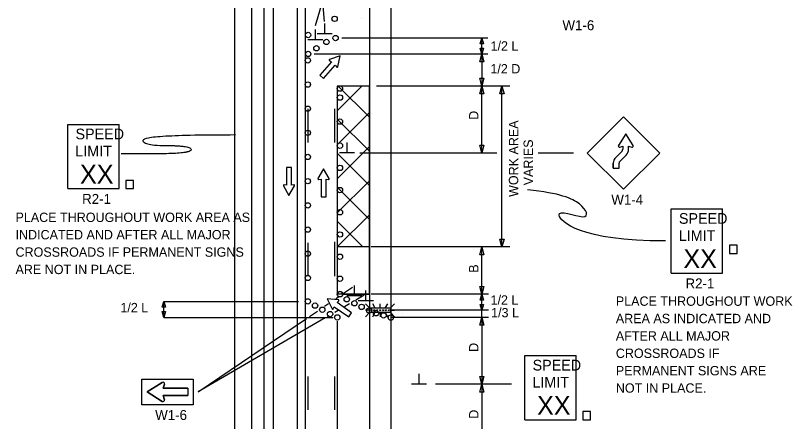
# Model space of a CAD drawing. Extents: x 16748 to 18296, y 7218 to 8262.
# Drawn here: x 16825 to 17405, y 7635 to 7938 of the extents above; entities that cross this region are included whole.
import ezdxf

# ---------------------------------------------------------------- set-up
doc = ezdxf.new("R2010")
doc.units = 0
for name, color, linetype in [('ALI_LEGAL_EX', 7, 'Continuous'), ('BORDER', 7, 'Continuous'), ('Level 42', 7, 'Continuous'), ('MT_SCRATCH_LEVEL_A', 7, 'Continuous'), ('MT_SCRATCH_LEVEL_E', 7, 'Continuous'), ('MT_STAGE_1A_NOTES', 7, 'Continuous'), ('PAVT_EDGE_EX', 7, 'Continuous'), ('TRAFFIC_SIGNS_PR', 7, 'Continuous'), ('TYPICAL_EX', 7, 'Continuous'), ('TYPICAL_TEXT_DIMEN_PR', 7, 'Continuous')]:
    doc.layers.add(name, color=color, linetype=linetype)

msp = doc.modelspace()

# ---------------------------------------------------------------- linework, layer by layer
at = {"layer": 'ALI_LEGAL_EX'}
msp.add_lwpolyline([(17089.08, 7668.47), (17089.08, 7653.92)], dxfattribs=at)
at = {"layer": 'BORDER'}
for p, q in [((17017.08, 8216.25), (17017.08, 7341.25)), ((17089.08, 8216.25), (17089.08, 7765.38)), ((17089.08, 7765.38), (17089.08, 7341.25))]:
    msp.add_line(p, q, dxfattribs=at)
at = {"layer": 'Level 42'}
for p, q in [((17083.1, 7935.93), (17083.1, 7935.93)), ((17063.22, 7923.81), (17063.22, 7923.81)), ((17087.08, 7729.95), (17087.08, 7729.95)), ((17073.87, 7718.33), (17073.87, 7718.33)), ((17079.7, 7715.13), (17079.7, 7715.13)), ((17108.91, 7717.79), (17108.91, 7717.79)), ((17114.05, 7715.71), (17114.05, 7715.71))]:
    msp.add_line(p, q, dxfattribs=at)
at = {"layer": 'MT_SCRATCH_LEVEL_A'}
for p, q in [((17041.08, 8216.25), (17041.08, 7341.25)), ((17089.09, 7885.6), (17065.08, 7885.6)), ((17066.01, 7773.88), (17066.06, 7774)), ((17065.08, 7709.73), (17065.08, 7341.25))]:
    msp.add_line(p, q, dxfattribs=at)
for points in [[(17065.08, 7885.6), (17065.08, 7765.51), (17065.08, 7729.95)], [(17043.08, 7868.47), (17043.08, 7843.47)], [(17063.08, 7868.47), (17063.08, 7843.47)], [(17043.08, 7768.47), (17043.08, 7743.47)], [(17063.08, 7769.08), (17063.08, 7743.47)], [(17043.08, 7668.47), (17043.08, 7643.47)], [(17063.08, 7668.47), (17063.08, 7643.47)]]:
    msp.add_lwpolyline(points, dxfattribs=at)
at = {"layer": 'MT_SCRATCH_LEVEL_E'}
for p, q in [((17067.13, 7908.18), (17059.25, 7905.49)), ((17067.13, 7908.18), (17059.25, 7905.49)), ((17065.43, 7900.01), (17067.13, 7908.18)), ((17065.43, 7900.01), (17067.13, 7908.18)), ((17060.69, 7903.71), (17051.91, 7893.78)), ((17060.69, 7903.71), (17051.91, 7893.78)), ((17054.71, 7891.31), (17063.5, 7901.23)), ((17054.71, 7891.31), (17063.5, 7901.23)), ((17059.15, 7904.65), (17060.69, 7903.71)), ((17059.15, 7904.65), (17060.69, 7903.71)), ((17063.5, 7901.23), (17064.62, 7899.82)), ((17063.5, 7901.23), (17064.62, 7899.82)), ((17051.91, 7893.78), (17054.71, 7891.31)), ((17051.91, 7893.78), (17054.71, 7891.31)), ((17030.82, 7824.7), (17027.08, 7824.7)), ((17027.08, 7824.7), (17027.08, 7811.45)), ((17030.82, 7824.7), (17027.08, 7824.7)), ((17027.08, 7824.7), (17027.08, 7811.45)), ((17030.82, 7811.45), (17030.82, 7824.7)), ((17030.82, 7811.45), (17030.82, 7824.7)), ((17054.76, 7823.64), (17050.65, 7816.4)), ((17054.76, 7823.64), (17050.65, 7816.4)), ((17058.91, 7816.4), (17054.76, 7823.64)), ((17058.91, 7816.4), (17054.76, 7823.64)), ((17051.14, 7815.72), (17052.91, 7816.03)), ((17051.14, 7815.72), (17052.91, 7816.03)), ((17052.91, 7816.03), (17052.91, 7802.78)), ((17052.91, 7816.03), (17052.91, 7802.78)), ((17056.65, 7802.78), (17056.65, 7816.03)), ((17056.65, 7816.03), (17058.43, 7815.72)), ((17056.65, 7802.78), (17056.65, 7816.03)), ((17056.65, 7816.03), (17058.43, 7815.72)), ((17024.82, 7811.08), (17028.97, 7803.84)), ((17024.82, 7811.08), (17028.97, 7803.84)), ((17027.08, 7811.45), (17025.3, 7811.76)), ((17027.08, 7811.45), (17025.3, 7811.76)), ((17028.97, 7803.84), (17033.08, 7811.08)), ((17028.97, 7803.84), (17033.08, 7811.08)), ((17032.6, 7811.76), (17030.82, 7811.45)), ((17032.6, 7811.76), (17030.82, 7811.45)), ((17052.91, 7802.78), (17056.65, 7802.78)), ((17052.91, 7802.78), (17056.65, 7802.78)), ((17057.62, 7726.47), (17061.2, 7718.96)), ((17065.93, 7725.73), (17057.62, 7726.47)), ((17057.62, 7726.47), (17061.2, 7718.96)), ((17065.93, 7725.73), (17057.62, 7726.47)), ((17064.94, 7723.67), (17066.21, 7724.94)), ((17064.94, 7723.67), (17066.21, 7724.94)), ((17075.81, 7716.08), (17064.94, 7723.67)), ((17075.81, 7716.08), (17064.94, 7723.67)), ((17062.03, 7718.96), (17062.79, 7720.6)), ((17062.03, 7718.96), (17062.79, 7720.6)), ((17062.79, 7720.6), (17073.66, 7713.01)), ((17062.79, 7720.6), (17073.66, 7713.01)), ((17073.66, 7713.01), (17075.81, 7716.08)), ((17073.66, 7713.01), (17075.81, 7716.08))]:
    msp.add_line(p, q, dxfattribs=at)
for centre, start, end in [((17059.4, 7905.05), 108.90425, 238.44322), ((17059.4, 7905.05), 108.90425, 238.44322), ((17064.97, 7900.11), 218.5156, 348.25253), ((17064.97, 7900.11), 218.5156, 348.25253), ((17051.06, 7816.18), 150.42484, 279.96381), ((17051.06, 7816.18), 150.42484, 279.96381), ((17058.5, 7816.18), 260.03619, 29.77312), ((17058.5, 7816.18), 260.03619, 29.77312), ((17025.23, 7811.3), 80.03619, 209.77312), ((17025.23, 7811.3), 80.03619, 209.77312), ((17032.67, 7811.3), 330.42484, 99.96381), ((17032.67, 7811.3), 330.42484, 99.96381), ((17065.88, 7725.26), 315.10498, 84.84191), ((17065.88, 7725.26), 315.10498, 84.84191), ((17061.62, 7719.16), 205.49363, 335.0326), ((17061.62, 7719.16), 205.49363, 335.0326)]:
    msp.add_arc(centre, 0.463, start, end, dxfattribs=at)
at = {"layer": 'MT_STAGE_1A_NOTES'}
msp.add_lwpolyline([(17069.08, 7729.95), (17069.42, 7729.95), (17076.66, 7729.95), (17077.86, 7729.95), (17086.42, 7729.95), (17089.08, 7729.95), (17089.08, 7765.38), (17065.08, 7765.38), (17065.08, 7729.95)], dxfattribs=at)
msp.add_arc((17067.08, 7729.95), 2, 0, 180, dxfattribs=at)
at = {"layer": 'PAVT_EDGE_EX'}
for p, q in [((16988.15, 8262.34), (16988.15, 7433.15)), ((17010.15, 8262.34), (17010.15, 7433.15)), ((17035.15, 8262.34), (17035.15, 7433.15)), ((17001.08, 8216.25), (17001.08, 7341.25)), ((17105.08, 8216.25), (17105.08, 7341.25)), ((17065.08, 7867.2), (17083.48, 7885.6)), ((17089.09, 7862.29), (17065.78, 7885.6)), ((17089.09, 7765.38), (17089.09, 7885.6)), ((17065.08, 7841.75), (17089.09, 7865.76)), ((17089.09, 7836.83), (17065.08, 7860.84)), ((17065.08, 7816.29), (17089.09, 7840.3)), ((17089.09, 7811.37), (17065.08, 7835.38)), ((17065.08, 7790.84), (17089.09, 7814.85)), ((17089.09, 7785.92), (17065.08, 7809.93)), ((17065.08, 7765.38), (17089.09, 7789.39)), ((17084.17, 7765.38), (17065.08, 7784.47))]:
    msp.add_line(p, q, dxfattribs=at)
at = {"layer": 'TRAFFIC_SIGNS_PR'}
for p, q in [((17278.82, 7862.71), (17251.66, 7835.56)), ((17305.97, 7835.56), (17278.82, 7862.71)), ((16863.72, 7856.93), (16902.12, 7856.93)), ((16863.72, 7808.93), (16863.72, 7856.93)), ((16902.12, 7808.93), (16902.12, 7856.93)), ((17273.16, 7832.3), (17277.87, 7837.02)), ((17277.87, 7837.02), (17273.16, 7832.3)), ((17251.66, 7835.56), (17278.82, 7808.4)), ((17276.21, 7829.25), (17280.93, 7833.97)), ((17276.21, 7829.25), (17280.93, 7833.97)), ((17278.82, 7808.4), (17305.97, 7835.56)), ((17271.29, 7824.18), (17271.29, 7827.88)), ((17275.61, 7824.18), (17275.61, 7827.88)), ((17271.29, 7824.18), (17275.61, 7824.18)), ((16863.72, 7808.93), (16902.12, 7808.93)), ((17314.58, 7793.74), (17352.98, 7793.74)), ((17314.58, 7745.74), (17314.58, 7793.74)), ((17352.98, 7745.74), (17352.98, 7793.74)), ((17314.58, 7745.74), (17352.98, 7745.74)), ((17086.12, 7722.8), (17088.94, 7719.98)), ((17093.21, 7719.98), (17091.58, 7722.8)), ((17097.02, 7719.98), (17097.02, 7722.8)), ((17101.16, 7719.98), (17102.78, 7722.8)), ((17105.11, 7719.98), (17107.93, 7722.8)), ((17088.94, 7717.95), (17086.12, 7717.95)), ((17086.12, 7713.1), (17088.94, 7715.92)), ((17090.57, 7717.95), (17090.57, 7717.95)), ((17091.55, 7713.1), (17093.18, 7715.92)), ((17092.75, 7717.95), (17092.75, 7717.95)), ((17094.92, 7717.95), (17094.92, 7717.95)), ((17097.02, 7715.92), (17097.02, 7713.1)), ((17097.1, 7717.95), (17097.1, 7717.95)), ((17099.27, 7717.95), (17099.27, 7717.95)), ((17102.81, 7713.1), (17101.18, 7715.92)), ((17101.44, 7717.95), (17101.44, 7717.95)), ((17103.62, 7717.95), (17103.62, 7717.95)), ((17105.11, 7717.95), (17107.93, 7717.95)), ((17105.11, 7715.92), (17107.93, 7713.1)), ((17205.24, 7684.03), (17243.64, 7684.03)), ((17205.24, 7636.03), (17205.24, 7684.03)), ((17243.64, 7636.03), (17243.64, 7684.03)), ((16934.23, 7664), (16923.07, 7656.9)), ((16935.07, 7659.7), (16935.91, 7662.76)), ((16923.07, 7656.9), (16934.23, 7649.8)), ((16953.47, 7659.7), (16935.07, 7659.7)), ((16953.47, 7659.7), (16953.47, 7654.1)), ((16935.91, 7651.04), (16935.07, 7654.1)), ((16935.07, 7654.1), (16953.47, 7654.1)), ((17205.24, 7636.03), (17243.64, 7636.03))]:
    msp.add_line(p, q, dxfattribs=at)
for points in [[(17286.08, 7841.29), (17280.6, 7849.9), (17275.12, 7841.29)], [(17286.08, 7841.29), (17280.6, 7849.9), (17275.12, 7841.29)], [(17276.08, 7840), (17278.44, 7840.64), (17278.43, 7838.35)], [(17276.08, 7839.99), (17276.91, 7840.22), (17278.44, 7840.64), (17278.43, 7838.35)], [(17282.75, 7838.28), (17282.75, 7840.64), (17285.12, 7840)], [(17271.29, 7827.88), (17271.29, 7824.18), (17275.61, 7824.18), (17275.61, 7827.88)], [(16934.23, 7649.8), (16923.07, 7656.9), (16934.23, 7664)], [(16935.91, 7662.76), (16935.07, 7659.7), (16953.47, 7659.7), (16953.47, 7654.1), (16935.07, 7654.1), (16935.91, 7651.04)]]:
    msp.add_lwpolyline(points, dxfattribs=at)
for points in [[(16907.14, 7808.93), (16912.73, 7808.93), (16912.73, 7815.1), (16907.14, 7815.1)], [(17358.14, 7760.51), (17363.73, 7760.51), (17363.73, 7766.68), (17358.14, 7766.68)], [(17104.88, 7716.15), (17089.17, 7716.15), (17089.17, 7719.75), (17104.88, 7719.75)], [(16957.47, 7647.3), (16919.07, 7647.3), (16919.07, 7666.5), (16957.47, 7666.5)], [(17248.66, 7636.03), (17254.25, 7636.03), (17254.25, 7642.2), (17248.66, 7642.2)]]:
    msp.add_lwpolyline(points, close=True, dxfattribs=at)
for centre, radius in [((17063.1, 7935.93), 2), ((17043.22, 7923.81), 2), ((17056.96, 7918.6), 2), ((17063.79, 7921.56), 2), ((17049.51, 7913.89), 2), ((17043.08, 7904.86), 2), ((17043.3, 7909.64), 2), ((17043.08, 7886.75), 2), ((17067.08, 7883.69), 2), ((17067.08, 7877.04), 2), ((17043.08, 7868.64), 2), ((17067.08, 7859.04), 2), ((17043.08, 7850.64), 2), ((17067.08, 7841.04), 2), ((17043.08, 7832.64), 2), ((17067.08, 7824.43), 2), ((17043.08, 7814.52), 2), ((17067.08, 7807.81), 2), ((17043.08, 7796.41), 2), ((17067.08, 7791.2), 2), ((17043.08, 7778.3), 2), ((17067.08, 7774.59), 2), ((17043.08, 7760.19), 2), ((17067.08, 7757.98), 2), ((17043.08, 7742.08), 2), ((17067.08, 7741.56), 2), ((17043.08, 7724.61), 2), ((17067.08, 7729.95), 2), ((17072.17, 7726.16), 2), ((17048.43, 7721.44), 2), ((17077.84, 7723.2), 2), ((17083.25, 7720.47), 2), ((17053.87, 7718.33), 2), ((17059.7, 7715.13), 2), ((17088.91, 7717.79), 2), ((17090.59, 7717.95), 0.379), ((17094.05, 7715.71), 2), ((17092.75, 7717.95), 0.379), ((17094.92, 7717.95), 0.379), ((17097.1, 7717.95), 0.379), ((17099.66, 7714.11), 2), ((17099.27, 7717.95), 0.379), ((17101.44, 7717.95), 0.379), ((17103.62, 7717.95), 0.379), ((17065.08, 7712.61), 2), ((17105.08, 7712.49), 2)]:
    msp.add_circle(centre, radius, dxfattribs=at)
for centre, radius, start, end in [((17275.85, 7840.83), 0.864, 147.52044, 285.3986), ((17275.85, 7840.83), 0.866, 147.52881, 285.38519), ((17276.58, 7838.35), 1.85, 314.21254, 0), ((17276.58, 7838.35), 1.85, 314.2123, 0.1238), ((17276.58, 7838.35), 6.17, 314.21254, 359.38189), ((17276.58, 7838.35), 6.17, 314.76872, 359.37555), ((17285.35, 7840.83), 0.866, 254.67989, 32.28036), ((17277.46, 7827.88), 6.17, 134.21172, 180), ((17277.46, 7827.89), 6.17, 134.21254, 180), ((17277.46, 7827.89), 6.17, 134.21254, 180), ((17277.46, 7827.88), 1.85, 132.37199, 180), ((17277.46, 7827.89), 1.85, 134.21254, 180), ((16934.83, 7663.05), 1.12, 344.67308, 122.46963), ((16934.83, 7663.05), 1.12, 344.67308, 122.46962), ((16934.83, 7650.74), 1.12, 237.53038, 15.32692), ((16934.83, 7650.74), 1.12, 237.53038, 15.32692)]:
    msp.add_arc(centre, radius, start, end, dxfattribs=at)
at = {"layer": 'TYPICAL_EX'}
for p, q in [((17055.67, 7924.69), (17055.67, 7932.47)), ((17048.75, 7920.18), (17048.75, 7927.97)), ((17061.3, 7924.69), (17050.05, 7924.69)), ((17054.37, 7920.18), (17043.12, 7920.18)), ((17072.41, 7835.59), (17072.41, 7843.37)), ((17078.03, 7835.59), (17066.78, 7835.59)), ((17077.86, 7728.64), (17077.86, 7736.43)), ((17086.42, 7725.05), (17086.42, 7732.84)), ((17083.48, 7728.64), (17072.23, 7728.64)), ((17092.04, 7725.05), (17080.79, 7725.05)), ((17126.21, 7662.61), (17126.21, 7670.39)), ((17131.83, 7662.61), (17120.58, 7662.61))]:
    msp.add_line(p, q, dxfattribs=at)
at = {"layer": 'TYPICAL_TEXT_DIMEN_PR'}
for p, q in [((17048.75, 7930.83), (17053.95, 7948.53)), ((17053.95, 7948.53), (17055.33, 7934.03)), ((17177.43, 7921.56), (17068.48, 7921.56)), ((17171.9, 7917.16), (17173.08, 7921.56)), ((17173.08, 7921.56), (17174.26, 7917.16)), ((17173.08, 7909.56), (17173.08, 7921.56)), ((17173.08, 7917.16), (17171.9, 7917.16)), ((17173.08, 7909.56), (17171.9, 7913.95)), ((17171.9, 7913.95), (17173.08, 7913.95)), ((17174.26, 7917.16), (17173.08, 7917.16)), ((17173.08, 7913.95), (17174.26, 7913.95)), ((17174.26, 7913.95), (17173.08, 7909.56)), ((17177.43, 7909.56), (17047.74, 7909.56)), ((17171.51, 7903.69), (17173.08, 7909.56)), ((17173.08, 7909.56), (17174.65, 7903.69)), ((17173.08, 7909.56), (17173.08, 7885.56)), ((17173.08, 7903.69), (17171.51, 7903.69)), ((17174.65, 7903.69), (17173.08, 7903.69)), ((17173.08, 7885.56), (17171.51, 7891.42)), ((17171.51, 7891.42), (17173.08, 7891.42)), ((17173.08, 7891.42), (17174.65, 7891.42)), ((17174.65, 7891.42), (17173.08, 7885.56)), ((17193.88, 7885.56), (17094.36, 7885.56)), ((17171.51, 7879.69), (17173.08, 7885.56)), ((17173.08, 7835.56), (17173.08, 7885.56)), ((17173.08, 7885.56), (17174.65, 7879.69)), ((17186.51, 7879.69), (17188.08, 7885.56)), ((17188.08, 7765.38), (17188.08, 7885.56)), ((17188.08, 7885.56), (17189.65, 7879.69)), ((17173.08, 7879.69), (17171.51, 7879.69)), ((17174.65, 7879.69), (17173.08, 7879.69)), ((17188.08, 7879.69), (17186.51, 7879.69)), ((17189.65, 7879.69), (17188.08, 7879.69)), ((17173.08, 7835.56), (17171.51, 7841.42)), ((17171.51, 7841.42), (17173.08, 7841.42)), ((17173.08, 7841.42), (17174.65, 7841.42)), ((17174.65, 7841.42), (17173.08, 7835.56)), ((17184.31, 7835.56), (17081.84, 7835.56)), ((17241.66, 7835.56), (17215.28, 7835.56)), ((17188.08, 7765.38), (17186.51, 7771.24)), ((17186.51, 7771.24), (17188.08, 7771.24)), ((17188.08, 7771.24), (17189.65, 7771.24)), ((17189.65, 7771.24), (17188.08, 7765.38)), ((17089.08, 7765.38), (17065.08, 7765.38)), ((17193.88, 7765.38), (17090.47, 7765.38)), ((17171.51, 7759.52), (17173.08, 7765.38)), ((17173.08, 7765.38), (17174.65, 7759.52)), ((17173.08, 7712.61), (17173.08, 7765.38)), ((17173.08, 7759.52), (17171.51, 7759.52)), ((17174.65, 7759.52), (17173.08, 7759.52)), ((17069.83, 7730.62), (17076.5, 7735.14)), ((17173.08, 7729.95), (17171.51, 7735.81)), ((17171.51, 7735.81), (17173.08, 7735.81)), ((17173.08, 7735.81), (17174.65, 7735.81)), ((17174.65, 7735.81), (17173.08, 7729.95)), ((17064.06, 7726.71), (17065.94, 7727.98)), ((17089.08, 7729.95), (17065.08, 7729.95)), ((17076.66, 7729.95), (17069.42, 7729.95)), ((17085.2, 7729.19), (17079.01, 7725.59)), ((17178.08, 7729.95), (17090.47, 7729.95)), ((17171.9, 7725.55), (17173.08, 7729.95)), ((17173.08, 7729.95), (17174.26, 7725.55)), ((16934.27, 7720.21), (16935.45, 7724.61)), ((16935.45, 7724.61), (16936.63, 7720.21)), ((16935.45, 7724.61), (17036.16, 7724.61)), ((16935.45, 7712.61), (16935.45, 7724.61)), ((17055.56, 7720.95), (17058.51, 7722.95)), ((17074.14, 7722.75), (17070.39, 7720.57)), ((17173.08, 7725.55), (17171.9, 7725.55)), ((17173.08, 7717.95), (17171.9, 7722.35)), ((17171.9, 7722.35), (17173.08, 7722.35)), ((17174.26, 7725.55), (17173.08, 7725.55)), ((17173.08, 7722.35), (17174.26, 7722.35)), ((17174.26, 7722.35), (17173.08, 7717.95)), ((16935.45, 7720.21), (16934.27, 7720.21)), ((16935.45, 7712.61), (16934.27, 7717.01)), ((16934.27, 7717.01), (16935.45, 7717.01)), ((16936.63, 7720.21), (16935.45, 7720.21)), ((16935.45, 7717.01), (16936.63, 7717.01)), ((16936.63, 7717.01), (16935.45, 7712.61)), ((17044.36, 7713.36), (17050.24, 7717.34)), ((17065.76, 7717.88), (17063.15, 7716.35)), ((17178.08, 7717.95), (17105.08, 7717.95)), ((16935.45, 7712.61), (17061.69, 7712.61)), ((17056.05, 7712.22), (16961.04, 7656.9)), ((16961.04, 7656.9), (17042.13, 7711.85)), ((17058.02, 7713.36), (17057.39, 7713)), ((17178.08, 7712.61), (17105.08, 7712.61)), ((17178.08, 7712.61), (17134.1, 7712.61)), ((17171.51, 7706.74), (17173.08, 7712.61)), ((17173.08, 7712.61), (17173.08, 7662.61)), ((17173.08, 7712.61), (17174.65, 7706.74)), ((17173.08, 7706.74), (17171.51, 7706.74)), ((17174.65, 7706.74), (17173.08, 7706.74)), ((17173.08, 7662.61), (17171.51, 7668.47)), ((17171.51, 7668.47), (17173.08, 7668.47)), ((17173.08, 7668.47), (17174.65, 7668.47)), ((17174.65, 7668.47), (17173.08, 7662.61)), ((17195.14, 7662.61), (17138.39, 7662.61)), ((17171.51, 7656.74), (17173.08, 7662.61)), ((17173.08, 7662.61), (17174.65, 7656.74)), ((17173.08, 7662.61), (17173.08, 7612.61)), ((17173.08, 7656.74), (17171.51, 7656.74)), ((17174.65, 7656.74), (17173.08, 7656.74))]:
    msp.add_line(p, q, dxfattribs=at)
for points, degree in [([(16988.94, 7849.03), (16919.86, 7849.03), (16919.86, 7841.15), (16955.82, 7841.15), (16955.82, 7835), (16907.52, 7835), (16903.59, 7835)], 2), ([(17310.32, 7769.87), (17246.15, 7769.43), (17217.11, 7799.46), (17255.92, 7782.43), (17249.22, 7798.42), (17231.65, 7805.29), (17207.15, 7808.11)], 3)]:
    msp.add_open_spline(points, degree=degree, dxfattribs=at)

# ---------------------------------------------------------------- texts
at = {"layer": 'TRAFFIC_SIGNS_PR'}
for s, height, p in [('W1-6', 7.44, (17233.32, 7927.39)), ('SPEED', 8, (16869.49, 7845.79)), ('LIMIT', 8, (16869.33, 7832.99)), ('XX', 14.031, (16872.83, 7812.69)), ('R2-1', 7.44, (16874.4, 7797.49)), ('W1-4', 7.44, (17269.82, 7796.96)), ('PLACE THROUGHOUT WORK AREA AS', 7, (16824.64, 7783.97)), ('SPEED', 8, (17320.35, 7782.6)), ('INDICATED AND AFTER ALL MAJOR', 7, (16824.64, 7770.97)), ('LIMIT', 8, (17320.19, 7769.8)), ('CROSSROADS IF PERMANENT SIGNS', 7, (16824.64, 7757.97)), ('XX', 14.031, (17323.69, 7749.49)), ('ARE NOT IN PLACE.', 7, (16824.64, 7744.97)), ('R2-1', 7.44, (17325.26, 7734.3)), ('PLACE THROUGHOUT WORK ', 7, (17273.18, 7721.28)), ('AREA AS INDICATED AND ', 7, (17273.18, 7708.28)), ('AFTER ALL MAJOR ', 7, (17273.18, 7695.28)), ('CROSSROADS IF ', 7, (17273.18, 7682.28)), ('SPEED', 8, (17211.01, 7672.89)), ('PERMANENT SIGNS ARE ', 7, (17273.18, 7669.28)), ('LIMIT', 8, (17210.84, 7660.09)), ('NOT IN PLACE. ', 7, (17273.18, 7656.28)), ('XX', 14.031, (17214.35, 7639.79)), ('W1-6', 7.44, (16929.01, 7635.86))]:
    msp.add_text(s, height=height, dxfattribs=at).set_placement(p)
at = {"layer": 'TYPICAL_TEXT_DIMEN_PR'}
for s, p in [('1/2 L', (17179.59, 7912.11)), ('1/2 D', (17179.45, 7895.04)), ('1/2 L', (17179.59, 7722.12)), ('1/2 L', (16903, 7716.44)), ('1/3 L', (17179.98, 7712.65))]:
    msp.add_text(s, height=7, dxfattribs=at).set_placement(p)
for s, p in [('D', (17170.52, 7860.35)), ('WORK AREA', (17200.25, 7802.71)), ('VARIES', (17211.25, 7811.36)), ('B', (17170.52, 7746.02)), ('D', (17170.52, 7686.82)), ('D', (17170.52, 7636.82))]:
    msp.add_text(s, height=7, rotation=90, dxfattribs=at).set_placement(p)

doc.saveas('drawing.dxf')
